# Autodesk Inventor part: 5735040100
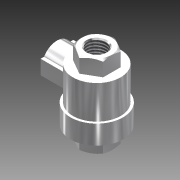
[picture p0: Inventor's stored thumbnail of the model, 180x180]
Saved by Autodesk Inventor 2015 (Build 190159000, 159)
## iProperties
Created: 2013-02
Part Number: 5735040100
Material: Generic
Document SubType Name: Modeling
Designer: Marci
Density: 1 g/cm^3
Appearance: Chrome - Polished
Translation Standard: STEP AP214IS
FileName: 5735040100
PreProcessor: PRO/ENGINEER BY PARAMETRIC TECHNOLOGY CORPORATION, 2009380
PostProcessor: Build: 160, Release: 2012 RTM - Date: Tue 03/01/2011
Sent Units: millimeter
Uncertainty: 0.001
Author: Marci
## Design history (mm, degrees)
node "57350401001"
thread "Thread1" dims "d0" = 10, "d1" = 0
thread "Thread2" dims "d2" = 10, "d3" = 0
thread "Thread3" dims "d4" = 10, "d5" = 0
node "5735040100"
node "Base1"
